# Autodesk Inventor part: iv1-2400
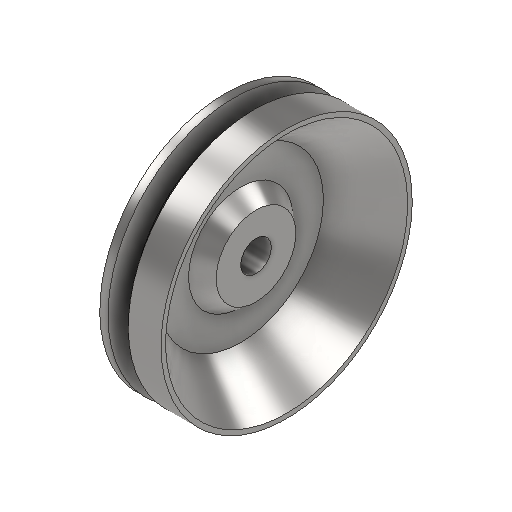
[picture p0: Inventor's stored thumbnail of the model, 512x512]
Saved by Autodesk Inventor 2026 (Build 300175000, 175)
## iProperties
Created: 2022-01
Part Number: iv1-2400
Material: Steel, Mild
Document SubType Name: Modeling
Designer: Lars Bertram Pedersen
Density: 7.85 g/cm^3
Appearance: Semi-Polished
Author: Lars Bertram Pedersen
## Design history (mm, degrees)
revolve "Revolution1" stored, may be unused: angle "d8" = 360 deg
body "Solid1"
sketch "Sketch1"
  geometry: L1 (0, 0)-(100, 0); L2 (0, 25)-(0, 205); L3 (0, 205)-(100, 205); L4 (100, 197.5)-(25, 135); L5 (25, 135)-(25, 85); L6 (25, 85)-(50, 65); L7 (50, 65)-(50, 25); L8 (50, 25)-(0, 25); L9 (100, 205)-(100, 197.5); L10 (0, 205)-(13.4, 205); L11 (13.4, 205)-(23.73, 175); L12 (23.73, 175)-(36.27, 175); L13 (36.27, 175)-(46.6, 205); L14 (100, 205)-(46.6, 205)
  constraints: 28 end point, 3 vertical, 2 horizontal, 2 parallel, 2 point on line, 2 vertical alignment, 1 collinear, 1 equal length, 1 perpendicular
  dimensions: "d0" = 100 distance of L1.start L1.end; "d1" = 410 diameter of L3 L1; "d2" = 270 diameter of L4.end L1; "d3" = 170 diameter of L5.end L1; "d4" = 50 distance of L7.end L2.start; "d5" = 50 diameter of L8 L1; "d6" = 130 diameter of L6.end L1; "d7" = 25 distance between parallel lines of L5 L2; "d9" = 395 diameter of L4.start L1; "d10" = 13.4 distance of L2.end L10.end; "d11" = 30 distance between parallel lines of L3 L12; "d12" = 33.2 distance of L13.end L10.end; "d14" = 38.0006 deg angle of L13 L11
